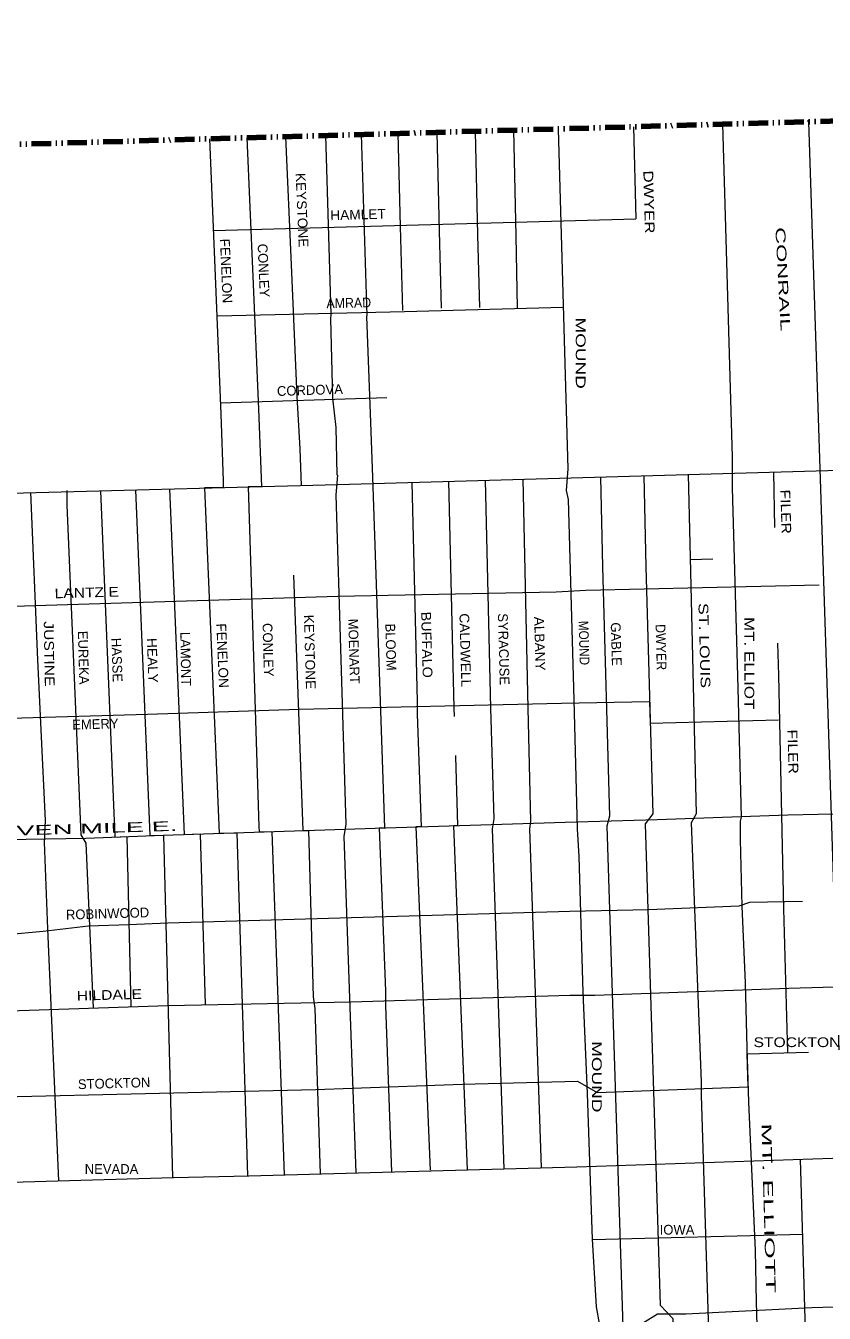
# Model space of a CAD drawing. Extents: x 34705 to 138605, y 34275 to 143551.
# Drawn here: x 96591 to 102735, y 133396 to 143301 of the extents above; entities that cross this region are included whole.
import ezdxf
from ezdxf.enums import TextEntityAlignment as Align

# ---------------------------------------------------------------- set-up
doc = ezdxf.new("R2010")
doc.units = 0
doc.header["$LTSCALE"] = 30
doc.linetypes.add('DASH_DOUBLE_DOT', pattern=[9.2, 5, -1.2, 0.3, -1.2, 0.3, -1.2])
for name, color, linetype, lineweight in [('1', 7, 'Continuous', 13), ('11', 7, 'Continuous', 13), ('50', 7, 'Continuous', 13), ('59', 7, 'DASH_DOUBLE_DOT', 106)]:
    doc.layers.add(name, color=color, linetype=linetype, lineweight=lineweight)

msp = doc.modelspace()

# ---------------------------------------------------------------- linework, layer by layer
at = {"layer": '1'}
for p, q in [((101952.18, 142542.88), (101952.18, 142542.87)), ((98293.41, 142438.51), (98293.41, 142438.51)), ((98591.79, 142447.02), (98591.79, 142447.02)), ((98897.63, 142455.75), (98897.63, 142455.74)), ((99174.06, 142463.63), (99174.06, 142463.63)), ((99455.1, 142471.65), (99455.1, 142471.65)), ((99755.44, 142480.22), (99755.44, 142480.21)), ((100049.38, 142488.6), (100049.38, 142488.6)), ((100343.93, 142497.01), (100343.93, 142497)), ((100687.63, 142506.81), (100687.63, 142506.8)), ((101268.24, 142523.36), (101285.19, 141816.74)), ((101269.26, 142523.4), (101269.26, 142523.39)), ((98034.59, 141725.71), (101285.19, 141816.74)), ((102343.33, 139867.34), (102353.13, 139440.56)), ((101702.68, 139193.96), (101878.36, 139199.46)), ((102549.39, 134581.2), (102627.53, 131943.02)), ((100950.57, 133964.19), (102572.66, 134004.9))]:
    msp.add_line(p, q, dxfattribs=at)
for points in [[(101951.16, 142542.84), (102026.05, 139982.57), (102027.19, 139747.46), (102070.92, 138206.13), (102096.57, 137212.1), (102088.55, 137181.64), (102088.55, 137040.55), (102101.37, 136527.5), (102127.02, 135937.49), (102139.84, 135437.27), (102152.66, 135020.41), (102203.95, 133878.88), (102210.36, 133484.48), (102236.01, 132573.81), (102280.88, 131566.95), (102287.29, 130736.46), (102312.94, 129351.22), (102325.76, 128511.11), (102332.17, 128310.71), (102120.61, 127913.09), (101741.51, 127224.19)], [(98292.39, 142438.48), (98337.9, 141372.02), (98381.38, 140351.32), (98405.03, 139756.59), (98303.29, 139753.91), (98384.57, 137141.55), (98386.78, 137098.68), (98483.4, 137101.87), (98532.03, 135735.48), (98579.78, 134460.24)], [(98590.77, 142446.99), (98632.81, 141461.81), (98676.28, 140449.12), (98700.16, 140046.99), (98710.36, 139764.61)], [(98896.61, 142455.71), (98939.14, 141082.41), (98935.92, 141045.54), (98951.96, 140436.29), (98977.6, 140210.23), (98984.01, 139846.28), (98990.42, 139844.68), (98977.6, 139692.37), (99054.54, 137159.19), (99038.5, 137064.6), (99083.38, 135748.31), (99131.76, 134475.5)], [(99173.04, 142463.6), (99214.81, 141069.59), (99211.6, 141064.78), (99240.46, 140319.25), (99259.69, 139827.05), (99351.48, 137130.38), (99310.07, 137129.1), (99359.05, 135876.57), (99359.05, 135761.14), (99406.44, 134483.1)], [(99454.08, 142471.62), (99471.25, 141755.79), (99490.44, 141109.67)], [(99754.42, 142480.18), (99772.57, 141723.72), (99788.59, 141127.3)], [(100048.36, 142488.57), (100067.48, 141691.66), (100083.5, 141133.72)], [(100342.91, 142496.97), (100362.39, 141685.25), (100372, 141127.3)], [(100686.61, 142506.77), (100763.07, 139892.78), (100750.25, 139726.04), (100764.21, 139657.68), (100807.95, 138116.35), (100833.59, 137122.31), (100846.42, 136910.68), (100878.47, 135865.34), (100910.53, 135087.76), (100948.99, 133965.46), (100981.05, 133446), (101025.93, 133189.47), (101070.8, 132721.32), (101083.62, 131967.78), (101064.39, 131839.52), (101083.62, 130646.68), (101062.79, 130537.65), (101070.8, 129322.37), (101096.45, 128437.36), (101109.27, 128110.29), (101077.21, 127975.62), (101097.94, 127180.93)], [(98004.52, 142430.27), (98049.41, 141378.44), (98092.88, 140312.84), (98108.9, 139799.79), (98109.7, 139748.82), (97965.15, 139745.02), (98078.26, 137088.49), (98214.03, 137092.97), (98298.2, 134452.52)], [(98067.58, 141068.95), (99504.35, 141101.66), (100725.28, 141136.56)], [(98089.36, 140399.14), (99369.91, 140440.84), (99369.91, 140440.84)], [(90124.26, 139559.75), (94346.64, 139649.89), (98992, 139772.02), (106174.4, 139976.31), (107517.43, 140011.2), (107726.73, 140051.91), (108720.92, 140086.81)], [(99560.54, 139788.19), (99602.67, 138103.52), (99602.67, 138007.32), (99632.54, 137139.01), (99591.99, 137137.77), (99702.05, 134496.14)], [(99844.83, 139796.28), (99884.76, 138052.22), (99886.98, 137987.94)], [(100126.73, 139804.29), (100166.85, 138052.22), (100192.49, 137199.27), (100179.67, 137122.31), (100269.33, 134506.97)], [(100415.04, 139812.49), (100455.34, 138052.22), (100474.58, 137180.03), (100468.16, 137122.31), (100557.92, 134516.99)], [(101012.58, 139829.49), (101029.14, 139139.23), (101082.02, 137220.12), (101062.79, 137143.16), (101184.6, 133292.08), (101299.99, 133253.61), (101344.87, 131938.91), (101312.82, 131861.96), (101402.37, 127909.11)], [(101345.73, 139838.97), (101362.51, 139139.23), (101415.39, 137239.36), (101357.69, 137162.4), (101473.09, 133458.83), (101569.26, 133356.22), (101588.49, 132740.56)], [(101686.97, 139848.67), (101702.3, 139209.78), (101748.77, 137239.36), (101710.3, 137168.81), (101787.23, 135177.54), (101787.23, 135074.93), (101857.44, 132846.86)], [(96628.05, 139709.87), (96682.45, 138424.18), (96708.09, 137885.48), (96740.15, 137186.44), (96733.74, 137019.7), (96759.38, 136352.74), (96842.08, 134415.01)], [(96906.84, 139726.08), (96906.84, 139613.81), (97015.82, 137075.81), (97054.29, 137011.68), (97110.83, 135743.72)], [(97165.76, 139724.01), (97276.91, 137059.89), (97367.96, 137063.42), (97400.48, 135753.32)], [(97436.1, 139731.11), (97546.52, 137070.35), (97649.81, 137074.34), (97720.63, 134440.97)], [(97697.55, 139737.99), (97809.2, 137079.6), (97931.95, 137083.66), (97971.07, 135772.36)], [(98652.23, 139075.1), (98723.13, 137109.79), (98765.53, 137111.19), (98801.29, 135831.68), (98814.11, 135741.9), (98856.74, 134467.9)], [(92682.41, 138751.35), (94393.16, 138777.51), (96079.2, 138824.04), (98992.72, 138912), (100672.95, 138946.9), (100899.7, 138958.53), (102696.21, 138999.24)], [(102375.98, 138550.81), (102381.87, 138305.53), (102421.93, 136508.26), (102453.6, 135399.2)], [(87159.37, 137713.45), (87306.68, 137719.03), (89565.4, 137803.36), (91507.99, 137861.52), (94143.16, 137922.6), (94718.74, 137928.41), (95515.25, 137945.86), (96736.18, 137980.75), (97526.88, 138004.02), (98695.49, 138044.73), (100713.65, 138089.07), (101391.4, 138101.2), (101395.97, 137937), (102382.26, 137961.12)], [(99897.35, 137686.88), (99897.58, 137680.26), (99911.81, 137147.6), (99883.29, 137146.72), (99987.28, 134499.17)], [(89232.24, 136885.29), (90112.2, 136931.38), (91366.5, 136935.99), (91366.5, 136935.99), (92803.93, 136935.99), (93200.15, 136949.81), (94080.12, 136972.86), (96283.49, 137037.38), (97052.88, 137051.21), (97647.21, 137074.25), (99279.05, 137128.15), (100742.47, 137173.13), (101449.66, 137193.58), (102455.25, 137230.38), (103387.26, 137250.83), (104070.94, 137267.18), (106012.63, 137324.43), (106127.09, 137336.7), (107898.11, 137377.59), (108625.74, 137393.94), (111271.54, 137492.08)], [(87295.02, 135921.83), (87625.72, 135939.39), (87643.16, 135921.94), (90253.63, 136049.89), (90980.37, 136055.71), (92102.47, 136049.89), (93156.24, 136067.34), (93179.49, 136108.05), (93313.22, 136183.66), (93499.26, 136183.66), (94301.59, 136212.74), (95301.59, 136236), (95603.92, 136241.82), (95882.99, 136259.26), (96726.01, 136334.87), (97074.85, 136375.58), (97382.99, 136387.21), (97685.31, 136398.84), (100777.6, 136489.71), (101382.26, 136501.34), (102079.93, 136530.42), (102161.33, 136559.5), (102568.3, 136565.32)], [(92946.94, 135660.23), (93342.28, 135666.05), (93342.28, 135660.23), (93505.08, 135747.47), (95619.1, 135806.18), (95623.65, 135694.55), (97684.58, 135762.73), (99091.56, 135791.81), (100777.6, 135844.15), (100969.46, 135844.15), (102463.65, 135896.5), (104488.36, 135956.11), (104581.38, 135961.93), (104837.19, 135944.48), (106052.31, 135985.19), (106156.96, 136008.45), (107431.31, 136044.53)], [(93808.07, 134868.35), (94685.31, 134904.17), (95655.4, 134915.95), (95650.24, 135042.49), (98277.6, 135105.54), (98824.11, 135117.17), (99103.18, 135128.8), (99952.02, 135157.88), (100835.74, 135181.15), (100986.91, 135093.91), (102149.08, 135136.83), (102141.27, 135390.64), (102614.82, 135403.61)], [(83101.01, 133486.56), (83891.71, 133858.78), (85025.43, 133905.3), (85083.57, 133934.38), (86840.83, 134002.71), (86990.55, 133998.36), (87997.81, 134043.42), (88660.6, 134066.69), (89340.84, 134089.95), (89858.28, 134107.4), (90311.77, 134159.74), (90515.26, 134258.61), (90840.84, 134305.14), (93673.68, 134351.66), (95138.8, 134363.3), (95679.5, 134380.74), (97726.73, 134441.09), (98308.13, 134452.72), (100831.39, 134522.51), (103555.22, 134615.57), (106139.42, 134688.42)], [(95130.25, 130321.18), (95381.61, 130325.96), (95576.64, 130393.64), (96452.28, 130819.66), (97383.65, 131301.42), (98108.05, 131675.68), (101094.19, 133205.57), (101336.98, 133321.03), (101452.41, 133392.7), (101671.32, 133392.7), (102639.49, 133440.47), (105214.69, 133516.12), (106171.95, 133548.83)]]:
    msp.add_lwpolyline(points, dxfattribs=at)
at = {"layer": '50'}
msp.add_line((102608.97, 142573.51), (102609.35, 142562.77), dxfattribs=at)
msp.add_lwpolyline([(103340.26, 126734.43), (103267.19, 128379.83), (103009.15, 131294.52), (102874.51, 134633.08), (102617.68, 142561.85)], dxfattribs=at)
at = {"layer": '59'}
msp.add_lwpolyline([(131989.06, 109708.72), (126856.28, 120352.83), (127983.73, 120601.28), (129321.71, 120998.46), (130612.42, 121494.12), (133722.19, 123216.65), (134563.84, 124776.42), (136438.38, 130047.1), (136736.54, 131235.05), (136773.12, 131974.15), (125584.57, 138103.26), (128512.62, 143301.1), (34921.35, 140631.52)], dxfattribs=at)

# ---------------------------------------------------------------- texts
at = {"layer": '11'}
for s, rotation, width, p in [('KEYSTONE', 272.458, 1.05, (98679.52, 141880.67)), ('DWYER   ', 271.472, 1.3, (101350.87, 141889.95)), ('HAMLET', 1.604, 1.05, (99148.67, 141811.07)), ('CONRAIL', 273, 1.8, (102379.55, 141348.94)), ('FENELON', 272.443, 1.05, (98095.72, 141413.39)), ('AMRAD', 1.304, 0.95, (99077.37, 141131.47)), ('MOUND', 270, 1.45, (100823.44, 140782.4)), ('FILER', 271.602, 1.2, (102402.18, 139561.47)), ('LANTZ E', 1.601, 1.2, (97061.11, 138903.02)), ('BUFFALO', 271.433, 1.1, (99639.59, 138538.2)), ('CALDWELL', 271.578, 1.05, (99935.5, 138495.92)), ('ST. LOUIS', 271.6, 1.35, (101775.98, 138532.14)), ('JUSTINE', 270.998, 1.2, (96733.83, 138468.35)), ('FENELON', 272.438, 1.05, (98067.92, 138453.85)), ('KEYSTONE', 271.579, 1.05, (98739.42, 138482.58)), ('ALBANY', 271.58, 1.05, (100508.47, 138546.19)), ('MOUND', 271.601, 0.9, (100849.49, 138551.72)), ('DWYER', 271.599, 0.95, (101441.94, 138519.36)), ('MT. ELLIOT', 270, 1.3, (102121.17, 138396.96)), ('HEALY', 271.999, 1.05, (97528.89, 138416.93)), ('FILER', 271.602, 1.2, (102456.59, 137715.43)), ('SEVEN MILE E.', 1.678, 2.1, (96999.01, 137085.85)), ('HILDALE', 1.678, 1.2, (97235.34, 135807.97)), ('MOUND', 270, 1.45, (100947.59, 135215.26)), ('MT. ELLIOTT', 271.574, 2.15, (102269.71, 134203.88))]:
    msp.add_text(s, height=75, rotation=rotation, dxfattribs=dict(at, width=width)).set_placement(p, align=Align.CENTER)
for s, rotation, p in [('CONLEY', 272.443, (98383.79, 141416.78)), ('CORDOVA', 1.865, (98778.6, 140460.95)), ('SYRACUSE', 271.576, (100231.42, 138504.15)), ('CONLEY', 271.577, (98418.5, 138498.74)), ('MOENART', 271.578, (99078.83, 138487.85)), ('BLOOM', 271.576, (99362.9, 138520.12)), ('GABLE', 271.597, (101097.02, 138543.05)), ('EUREKA', 271.512, (96997.7, 138439.01)), ('HASSE', 272, (97255.24, 138420.89)), ('LAMONT', 271.001, (97784.19, 138428.75)), ('EMERY', 1.601, (97127.69, 137891.47)), ('ROBINWOOD', 1.676, (97221.47, 136433.8)), ('STOCKTON', 1.676, (97271.82, 135128.19))]:
    msp.add_text(s, height=75, rotation=rotation, dxfattribs=at).set_placement(p, align=Align.CENTER)
at = {"layer": '11', "width": 1.2}
msp.add_text('STOCKTON  ', height=75, dxfattribs=at).set_placement((102558.96, 135443.68), align=Align.CENTER)
at = {"layer": '11'}
for s, p in [('NEVADA', (97250.92, 134468.61)), ('IOWA', (101602.51, 134001.21))]:
    msp.add_text(s, height=75, dxfattribs=at).set_placement(p, align=Align.CENTER)

doc.saveas('drawing.dxf')
